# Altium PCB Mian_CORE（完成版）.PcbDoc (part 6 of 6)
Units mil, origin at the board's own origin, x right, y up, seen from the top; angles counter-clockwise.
Board outline 2755.91 x 1771.65 mil, 4 copper layers (TOP, GND02, PWR03, BOTTOM); 61 components, 130 nets, 4907 pads, 497 vias.
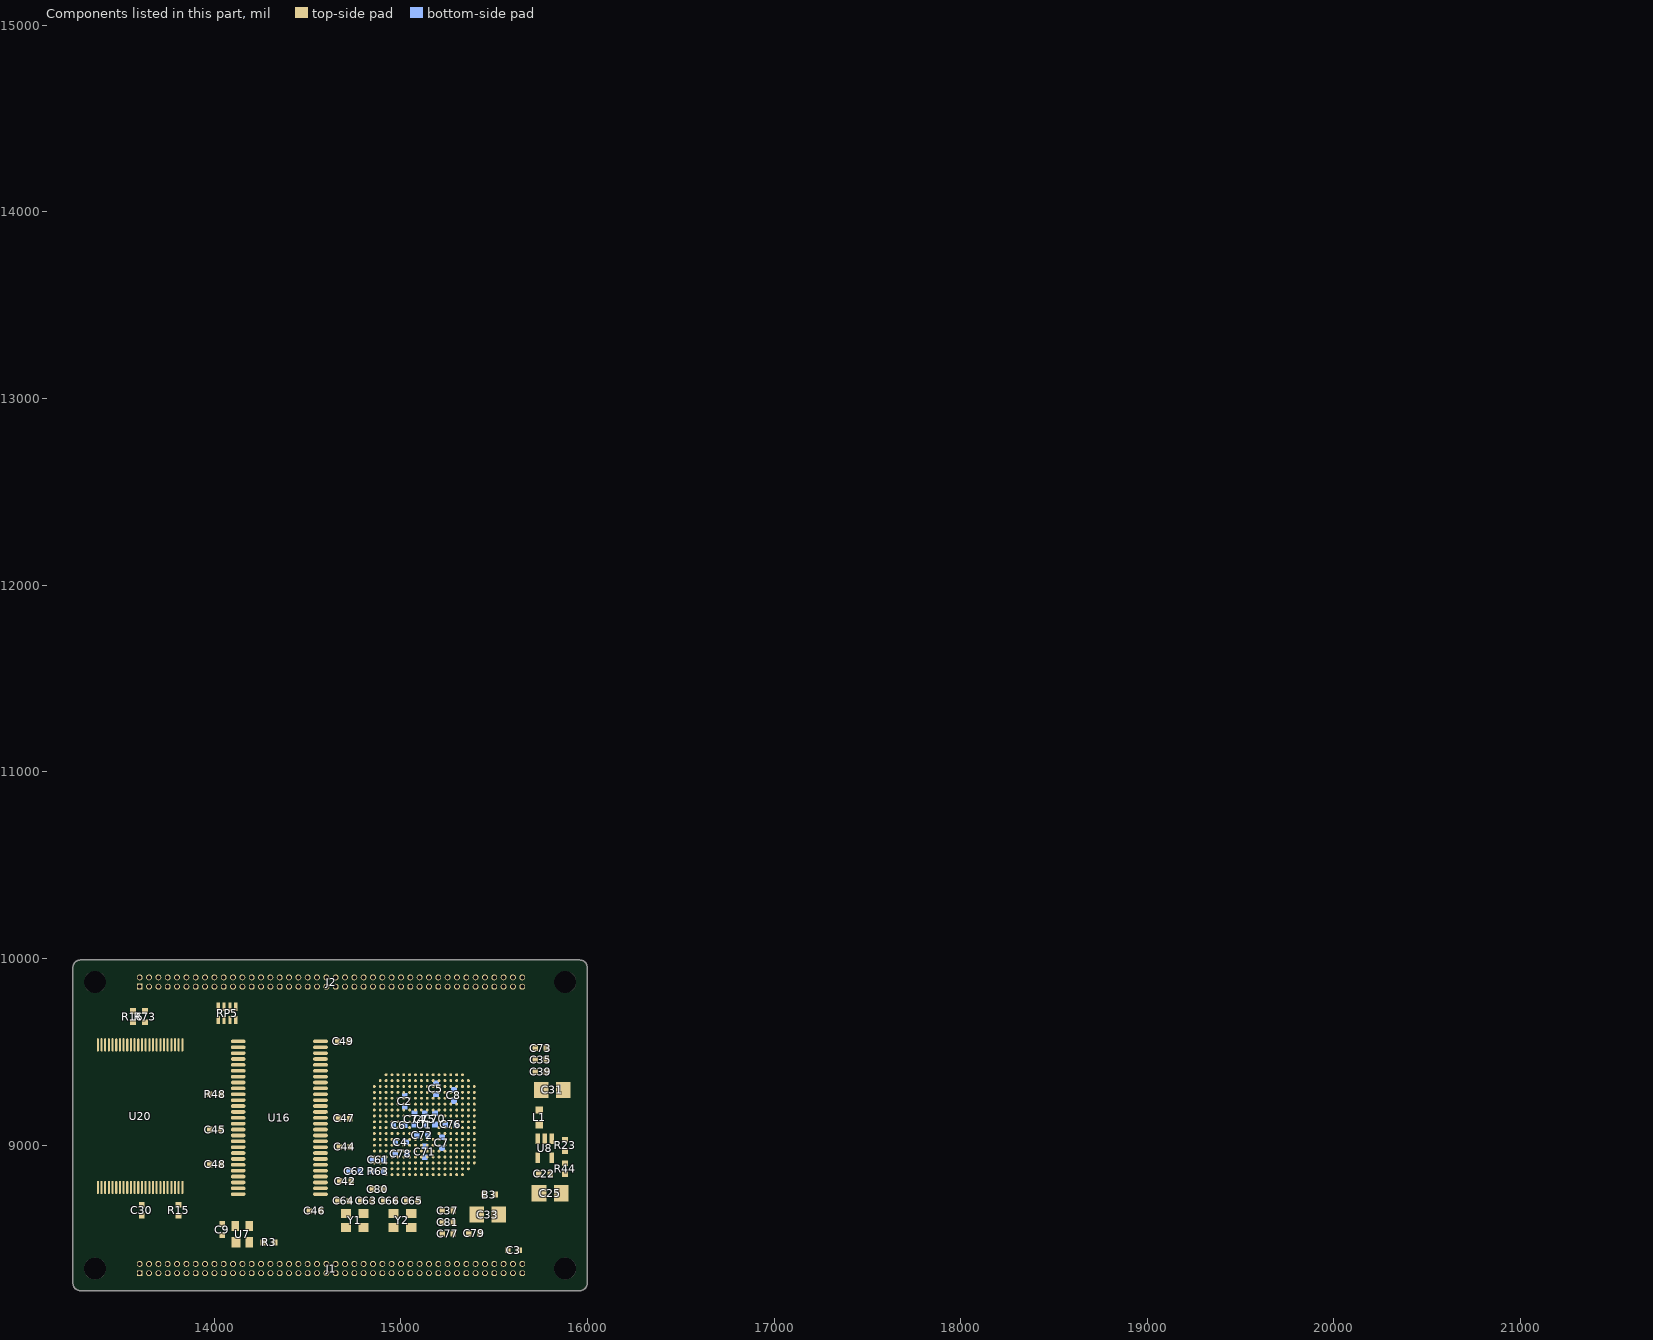
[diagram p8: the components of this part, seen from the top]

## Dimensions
13243,8259.37 to 15998.91,8259.37 on Mechanical 1
13282.37,8220 to 13282.37,9991.65 on Mechanical 1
